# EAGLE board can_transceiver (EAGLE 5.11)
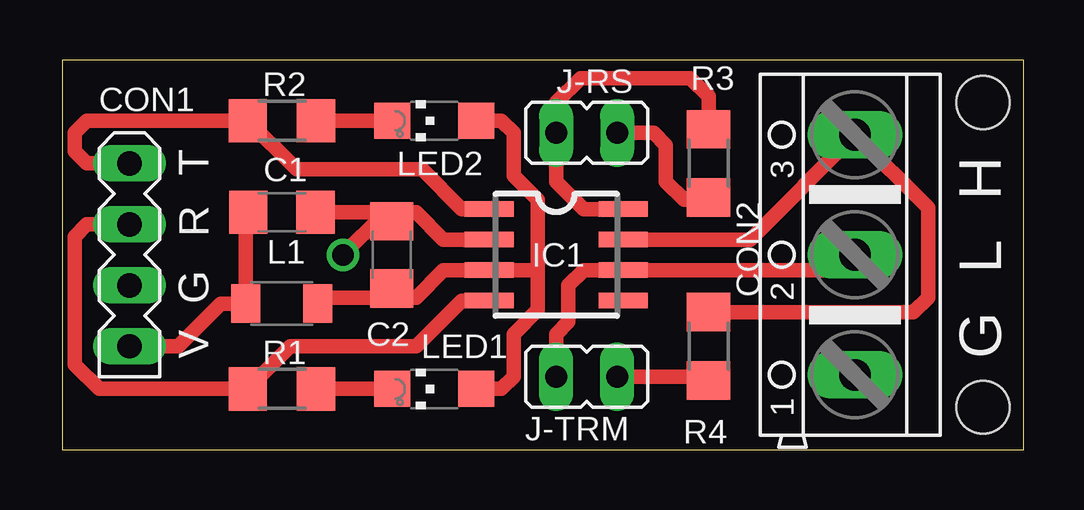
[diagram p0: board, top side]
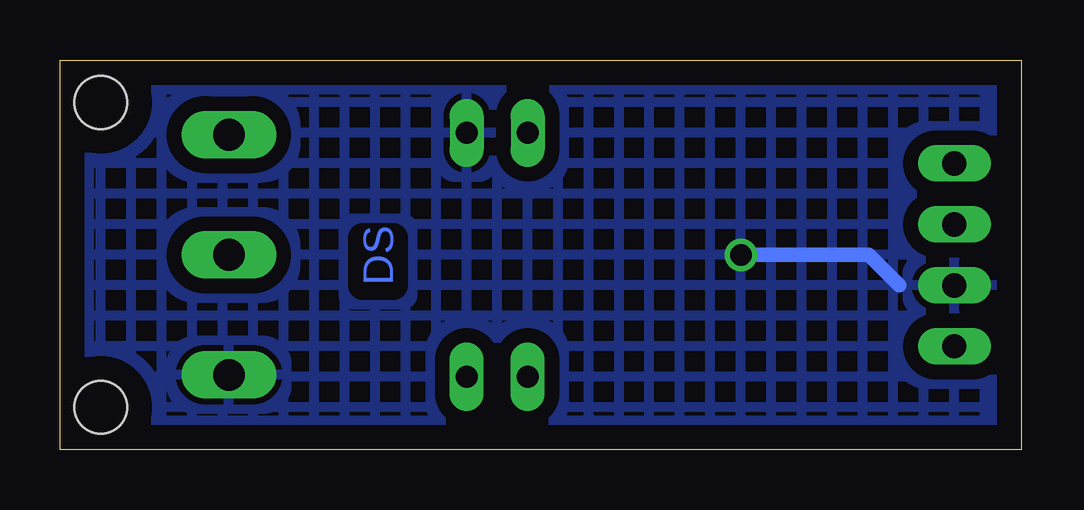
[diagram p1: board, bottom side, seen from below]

Size 40.06 x 16.25 mm. Coordinates in mm from the lower left corner, seen from the top.
Outline: 0,0 40.06,0 40.06,16.25 0,16.25 0,0
Copper layers (1*16): Top 0.035mm / dielectric 1.5mm / Bottom 0.035mm
Design rules "default": minimum track width 10mil, minimum drill 24mil, track to track 8mil, track to pad 8mil, pad to pad 8mil, via to via 8mil, smd to smd 8mil, copper to edge 40mil, drill to drill 8mil, minimum pad ring 10mil, minimum via ring 8mil, stop-mask expansion 4mil, vias tented up to drill 0mil, thermal gap 10mil
Holes 2.2 mm at 38.35,1.78 38.35,14.48

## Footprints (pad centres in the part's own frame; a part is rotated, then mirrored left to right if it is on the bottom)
C1206 = smd 1.6 x 1.8: 1 -1.4,0; 2 1.4,0
MA04-1 = drill 1.016 long: 1 -3.81,0; 2 -1.27,0; 3 1.27,0; 4 3.81,0
AK500/3 = drill 1.321 long: 1 -5.004,0; 2 0,0; 3 5.004,0
SO8 = smd 0.635 x 2.032: 1 -1.905,-2.794; 2 -0.635,-2.794; 3 0.635,-2.794; 4 1.905,-2.794; 5 1.905,2.794; 6 0.635,2.794; 7 -0.635,2.794; 8 -1.905,2.794
JP1 = drill 0.914 long: 1 0,-1.27; 2 0,1.27
L3216C = smd 1.2 x 1.6: 1 -1.5,0; 2 1.5,0
CHIPLED_1206 = smd 1.5 x 1.5: A 0,-1.75; C 0,1.75
R1206 = smd 1.6 x 1.803: 1 -1.422,0; 2 1.422,0

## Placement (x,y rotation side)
C1  100nF  [C1206]  9.14,9.91 0 top
C2  100nF  [C1206]  13.72,8.13 90 top
CON1  [MA04-1]  2.79,8.13 90 top
CON2  [AK500/3]  33.02,8.13 90 top
IC1  MCP2551  [SO8]  20.57,8.13 270 top
J-RS  [JP1]  21.84,13.21 270 top
J-TRM  [JP1]  21.84,3.05 90 top
L1  1uH  [L3216C]  9.14,6.1 0 top
LED1  [CHIPLED_1206]  15.49,2.54 90 top
LED2  [CHIPLED_1206]  15.49,13.72 90 top
R1  1k  [R1206]  9.14,2.54 180 top
R2  1k  [R1206]  9.14,13.72 180 top
R3  22k  [R1206]  26.92,11.94 270 top
R4  120R  [R1206]  26.92,4.32 90 top

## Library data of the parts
C1 C2 L1 R1-R4 = rcl
CON1 = con-lstb
CON2 = con-ptr500
IC1 = MCP2551
J-RS J-TRM = jumper
LED1 LED2 = led

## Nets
GND: C1.2 C2.2 CON1.2 CON2.1 IC1.2 J-RS.2 R3.2
N$1: CON2.3 IC1.7 R4.2
N$2: CON2.2 IC1.6 J-TRM.2
N$3: J-TRM.1 R4.1
N$4: IC1.8 J-RS.1 R3.1
N$6: LED1.C R1.1
N$9: C1.1 CON1.1 L1.1
N$10: CON1.3 IC1.4 R1.2
N$11: CON1.4 IC1.1 R2.2
N$12: LED2.C R2.1
VDD: C2.1 IC1.3 L1.2 LED1.A LED2.A

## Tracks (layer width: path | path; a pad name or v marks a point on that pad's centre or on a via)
GND  (via drill 0.9)
  Top 0.61: J-RS.2 24.64,13.21 25.15,12.7 25.15,11.18 25.91,10.41 26.82,10.41 R3.2 | IC1.2 15.87,8.76 14.73,9.91 13.59,9.91 C2.2 13.34,9.91 | 13.34,9.91 13.34,9.78 v11.68,8.13 | 13.34,9.91 C1.2
  Bottom 0.61: v11.68,8.13 6.35,8.13 5.08,6.86
  pour Bottom (isolate 0.61, hatched): 0,16.26 40.13,16.26 40.13,0 0,0
N$1
  Top 0.61: IC1.7 28.65,8.76 CON2.3 36.07,10.08 36.07,6.35 35.46,5.74 R4.2
N$2
  Top 0.61: CON2.2 32.39,7.49 IC1.6 21.72,7.49 21.08,6.86 21.08,5.33 20.57,4.83 J-TRM.2
N$3
  Top 0.61: J-TRM.1 26.77,3.05 R4.1
N$4
  Top 0.61: R3.1 26.92,14.73 26.16,15.49 21.59,15.49 20.57,14.48 J-RS.1 20.57,11.18 21.72,10.03 IC1.8
N$6
  Top 0.61: R1.1 LED1.C
N$9
  Top 0.61: C1.1 7.64,9.81 L1.1 6.6,6.1 4.83,4.32 CON1.1
N$10
  Top 0.61: CON1.3 1.02,9.4 0.51,8.89 0.51,3.56 1.52,2.54 R1.2 9.5,4.32 14.73,4.32 16.64,6.22 IC1.4
N$11
  Top 0.61: CON1.4 1.02,11.94 0.51,12.45 0.51,13.21 1.02,13.72 R2.2 9.75,11.68 14.99,11.68 16.64,10.03 IC1.1
N$12
  Top 0.61: R2.1 LED2.C
VDD
  Top 0.61: L1.2 10.64,6.33 10.67,6.35 13.34,6.35 C2.1 14.09,6.35 14.73,6.35 15.87,7.49 IC1.3 19.69,7.49 19.81,7.62 | LED2.A 18.29,13.72 18.8,13.21 18.8,11.43 19.81,10.41 19.81,7.62 | 19.81,7.62 19.81,5.84 18.8,4.83 18.8,3.05 18.29,2.54 LED1.A

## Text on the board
Bottom: DS
tPlace: T | H | R | L | G | V | G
